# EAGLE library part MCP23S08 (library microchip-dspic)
8-Bit I/O Expander with SPI Interface
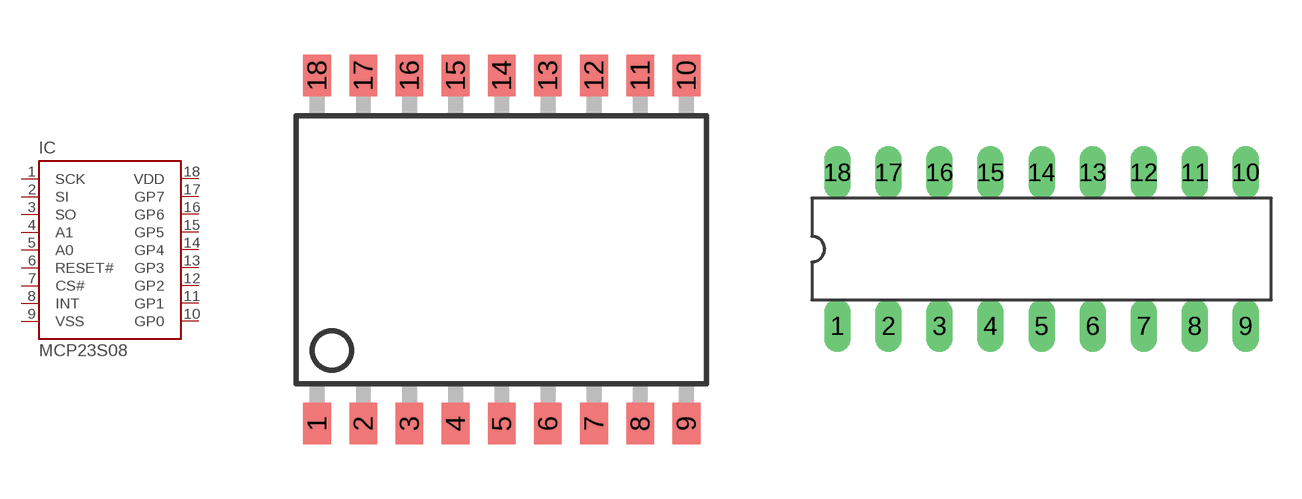
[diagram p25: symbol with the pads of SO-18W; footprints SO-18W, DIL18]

Designator prefix IC

## MCP23S08SO  [SO-18W]
1  SCK  in
2  SI  in
3  SO  out
4  A1  in
5  A0  in
6  RESET#  in
7  CS#  in
8  INT  out
9  VSS  pwr
10  GP0
11  GP1
12  GP2
13  GP3
14  GP4
15  GP5
16  GP6
17  GP7
18  VDD  pwr

## MCP23S08P  [DIL18]
Pads as for SO-18W

## MCP23S08SS  [SSOP20]
1  SCK  in
2  SI  in
3  SO  out
4  A1  in
5  A0  in
6  RESET#  in
7  CS#  in
8  INT  out
9  VSS  pwr
12  GP0
13  GP1
14  GP2
15  GP3
16  GP4
17  GP5
18  GP6
19  GP7
20  VDD  pwr

## Footprint SO-18W (pad centres in mm)
Small Outline Wide Plastic Gull Wing 300-mil body, package type SO
smd 0.762 x 1.143: 1 -5.08,-4.788; 2 -3.81,-4.788; 3 -2.54,-4.788; 4 -1.27,-4.788; 5 0,-4.788; 6 1.27,-4.788; 7 2.54,-4.788; 8 3.81,-4.788; 9 5.08,-4.788; 10 5.08,4.788; 11 3.81,4.788; 12 2.54,4.788; 13 1.27,4.788; 14 0,4.788; 15 -1.27,4.788; 16 -2.54,4.788; 17 -3.81,4.788; 18 -5.08,4.788

## Footprint DIL18 (pad centres in mm)
Dual In Line package type P
drill 0.813 long: 1 -10.16,-3.81; 2 -7.62,-3.81; 3 -5.08,-3.81; 4 -2.54,-3.81; 5 0,-3.81; 6 2.54,-3.81; 7 5.08,-3.81; 8 7.62,-3.81; 9 10.16,-3.81; 10 10.16,3.81; 11 7.62,3.81; 12 5.08,3.81; 13 2.54,3.81; 14 0,3.81; 15 -2.54,3.81; 16 -5.08,3.81; 17 -7.62,3.81; 18 -10.16,3.81

## Footprint SSOP20 (pad centres in mm)
Shrink Small Outline Package package type SS
smd 0.4 x 1.5: 1 -2.925,-3.625; 2 -2.275,-3.625; 3 -1.625,-3.625; 4 -0.975,-3.625; 5 -0.325,-3.625; 6 0.325,-3.625; 7 0.975,-3.625; 8 1.625,-3.625; 9 2.275,-3.625; 10 2.925,-3.625; 11 2.925,3.625; 12 2.275,3.625; 13 1.625,3.625; 14 0.975,3.625; 15 0.325,3.625; 16 -0.325,3.625; 17 -0.975,3.625; 18 -1.625,3.625; 19 -2.275,3.625; 20 -2.925,3.625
